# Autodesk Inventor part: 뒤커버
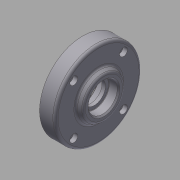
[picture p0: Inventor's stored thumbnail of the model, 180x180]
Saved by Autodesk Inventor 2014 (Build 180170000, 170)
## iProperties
Company: 한국ATC센터
Created: 2015-12
Part Number: 뒤커버
Document SubType Name: Modeling
Designer: mdu
Density: 2.71 g/cm^3
Mass: 97.9591 g
Surface Area: 115.525 cm^2
Volume: 36.1473 cm^3
Material: 알루미늄-6061
Appearance: 알루미늄 - 평지
Author: mdu
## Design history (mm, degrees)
sketch "스케치1"
  geometry: L1 (-10.5, 0)-(10.5, 0); L2 (10.5, 0)-(10.5, 22.5); L3 (10.5, 22.5)-(5.5, 22.5); L4 (5.5, 22.5)-(5.5, 32.5); L5 (5.5, 32.5)-(-6.5, 32.5); L6 (-6.5, 32.5)-(-6.5, 17.5); L7 (-6.5, 17.5)-(-10.5, 15.191); L8 (-10.5, 15.191)-(-10.5, 0); 2 further points
  constraints: 16 end point, 3 parallel, 3 perpendicular, 1 coincident, 1 horizontal, 1 midpoint
  dimensions: "d0" = 21 distance of L1.start L1.end; "d1" = 65 diameter of L5 L1; "d2" = 45 diameter of L3 L1; "d3" = 35 diameter of L6.end L1; "d4" = 120 deg angle of L7 L6; "d5" = 12 distance of L4.end L5.end; "d6" = 5 distance of L2.end L3.end
revolve "회전1" sketch "스케치1" stored, may be unused: angle "d7" = 90 deg
sketch "스케치2"
  geometry: L1 (0, 0)-(32.5, 0); L2 (0, 0)-(18.738, 18.738); 1 further point
  constraints: 4 end point, 1 horizontal, 1 horizontal alignment, 1 other
  dimensions: "d8" = 45 deg angle of L1 L2; "d9" = 26.5 distance of L1.start L2.end
hole "구멍1" sketch "스케치2" at (18.738, 18.738) diameter "d10" = 3.4; stored, may be unused: countersink angle "d14" = 90 deg, drill point angle "d16" = 118 deg; dims "d11" = 6, "d12" = 6, "d13" = 3.3, "d15" = 8
fillet "모깎기1" dims "d20" = 2
hole "구멍2" diameter "d23" = 15; stored, may be unused: countersink angle "d27" = 90 deg, drill point angle "d29" = 0 deg; dims "d21" = 10, "d22" = 10, "d24" = 6, "d25" = 35, "d26" = 11, "d28" = 14
chamfer "모따기1" distance "d39" = 1; stored, may be unused: second distance "d40" = 2, angle "d41" = 45 deg
fillet "모깎기2" dims "d42" = 0.3
hole "구멍4" diameter "d46" = 17; stored, may be unused: countersink angle "d50" = 90 deg, drill point angle "d52" = 118 deg; dims "d44" = 10, "d45" = 10, "d47" = 6, "d48" = 22, "d49" = 7.3, "d51" = 8
chamfer "모따기2" distance "d53" = 1; stored, may be unused: second distance "d54" = 2, angle "d55" = 45 deg
fillet "모깎기3" dims "d56" = 0.3
node "솔리드1"
pattern_circular "원형 패턴1" dims angle "d18" = 360 deg
